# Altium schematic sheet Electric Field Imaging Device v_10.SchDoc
size A3
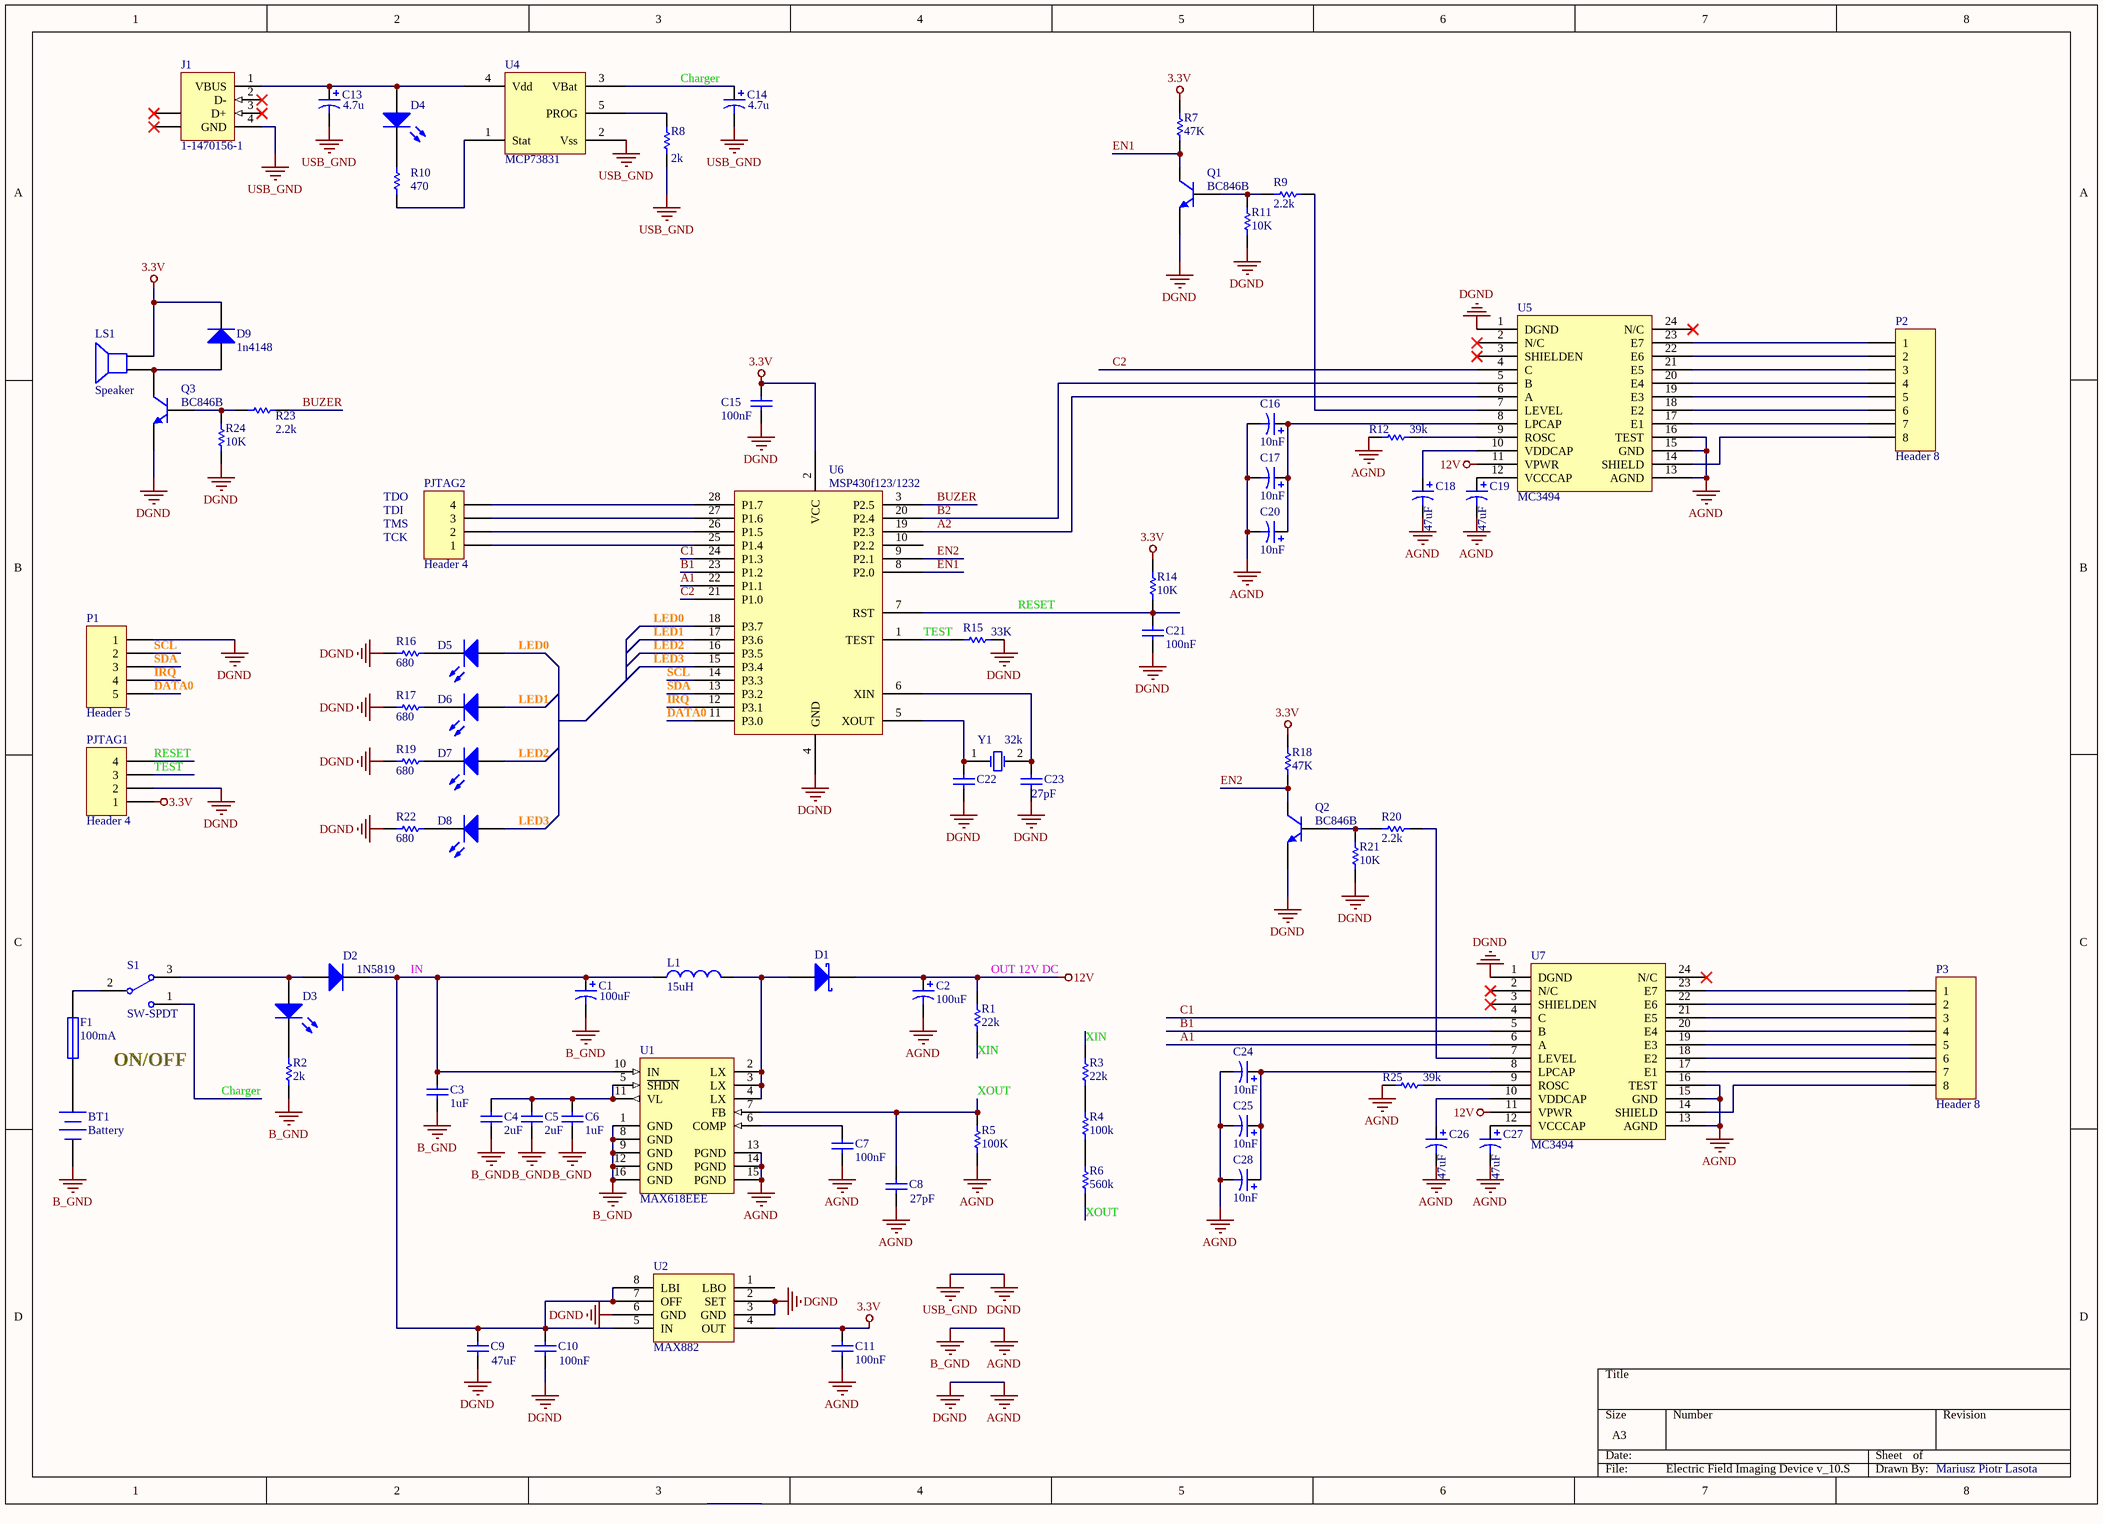
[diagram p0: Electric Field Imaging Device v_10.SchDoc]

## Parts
BT1  Battery  [6332[2512]]
C1  value 100uF  [##C_tantal_1]  (hidden comment: Cap Pol1)
C2  value 100uF  [##C_tantal_1]  (hidden comment: Cap Pol1)
C3  value 1uF  [1206]  (hidden comment: Cap)
C4  value 2uF  [1206]  (hidden comment: Cap)
C5  value 2uF  [1206]  (hidden comment: Cap)
C6  value 1uF  [1206]  (hidden comment: Cap)
C7  value 100nF  [0805]  (hidden comment: Cap)
C8  value 27pF  [0805]  (hidden comment: Cap)
C9  value 47uF  [C 100UF]  (hidden comment: Cap)
C10  value 100nF  [0805]  (hidden comment: Cap)
C11  value 100nF  [0805]  (hidden comment: Cap)
C13  value 4.7u  [##C_tantal_1]  (hidden comment: Cap Pol1)
C14  value 4.7u  [##C_tantal_1]  (hidden comment: Cap Pol1)
C15  value 100nF  [0805]  (hidden comment: Cap)
C16  value 10nF  [1206]  (hidden comment: Cap Pol1)
C17  value 10nF  [1206]  (hidden comment: Cap Pol1)
C18  value 47uF  [6332[2512]]  (hidden comment: Cap Pol1)
C19  value 47uF  [6332[2512]]  (hidden comment: Cap Pol1)
C20  value 10nF  [1206]  (hidden comment: Cap Pol1)
C21  value 100nF  [0805]  (hidden comment: Cap)
C22  27pF  [0805]  (value not drawn)
C23  27pF  [0805]
C24  value 10nF  [1206]  (hidden comment: Cap Pol1)
C25  value 10nF  [1206]  (hidden comment: Cap Pol1)
C26  value 47uF  [6332[2512]]  (hidden comment: Cap Pol1)
C27  value 47uF  [6332[2512]]  (hidden comment: Cap Pol1)
C28  value 10nF  [1206]  (hidden comment: Cap Pol1)
D1  D Schottky  [##DLAWIK_SMD_5819]  (value not drawn)
D2  NAME: 1N5819  [##DLAWIK_SMD]  (hidden comment: Diode)
D3  LED0  [0805]  (value not drawn)
D4  LED0  [0805]  (value not drawn)
D5  LED1  [0805]  (value not drawn)
D6  LED1  [0805]  (value not drawn)
D7  LED1  [0805]  (value not drawn)
D8  LED1  [0805]  (value not drawn)
D9  NAME: 1n4148  [0805DIODE]  (hidden comment: Diode)
F1  100mA  [3.2X1.6X1.1]
J1  1-1470156-1  [USB_MALE]
L1  value 15uH  [##DLAWIK_SMD]  (hidden comment: Inductor)
LS1  Speaker  [D_330uH_pionowy]
P1  Header 5  [HDR1X5]
P2  Header 8  [HDR1X8]
P3  Header 8  [HDR1X8]
PJTAG1  Header 4  [GOLDPIN4_2.54]
PJTAG2  Header 4  [GOLDPIN4_2.54]
Q1  BC846B  [SOT23_N]
Q2  BC846B  [SOT23_N]
Q3  BC846B  [SOT23_N]
R1  value 22k  [0805]  (hidden comment: Res1)
R2  value 2k  [0805]  (hidden comment: Res1)
R3  value 22k  [0805]  (hidden comment: Res1)
R4  value 100k  [0805]  (hidden comment: Res1)
R5  value 100K  [0805]  (hidden comment: Res1)
R6  value 560k  [0805]  (hidden comment: Res1)
R7  value 47K  [1206]  (hidden comment: Res1)
R8  value 2k  [0805]  (hidden comment: Res1)
R9  value 2.2k  [1206]  (hidden comment: Res1)
R10  value 470  [0805]  (hidden comment: Res1)
R11  value 10K  [1206]  (hidden comment: Res1)
R12  value 39k  [0805]  (hidden comment: Res1)
R14  value 10K  [0805]  (hidden comment: Res1)
R15  value 33K  [0805]  (hidden comment: Res1)
R16  value 680  [0805]  (hidden comment: Res1)
R17  value 680  [0805]  (hidden comment: Res1)
R18  value 47K  [1206]  (hidden comment: Res1)
R19  value 680  [0805]  (hidden comment: Res1)
R20  value 2.2k  [1206]  (hidden comment: Res1)
R21  value 10K  [1206]  (hidden comment: Res1)
R22  value 680  [0805]  (hidden comment: Res1)
R23  value 2.2k  [0805]  (hidden comment: Res1)
R24  value 10K  [0805]  (hidden comment: Res1)
R25  value 39k  [0805]  (hidden comment: Res1)
S1  SW-SPDT  [HDR1X3]
U1  MAX618EEE  [SOP16]
U2  MAX882  [SOP8_L]
U4  MCP73831  [soic_MCP73831]
U5  MC3494  [TOUCH_PANEL]
U6  MSP430f123/1232  [MSP430F1232]
U7  MC3494  [TOUCH_PANEL]
Y1  val: 32k  [kwarc_32K]  (hidden comment: XTAL)

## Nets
3.3V: C11.2 C15.2 D9.2(K) LS1.2 PJTAG1.1 R7.2 R14.2 R18.2 U2.4(OUT) U6.2(VCC)
12V: C2.1 D1.2(K) R1.2 U5.11(VPWR) U7.11(VPWR)
AGND: BT1.2(-) C1.2 C2.2 C3.1 C4.1 C5.1 C6.1 C7.1 C8.1 C9.1 C10.1 C11.1 C13.2 C14.2 C15.1 C16.2 C17.2 C18.2 C19.2 C20.2 C21.2 C22.1 C23.1 C24.2 C25.2 C26.2 C27.2 C28.2 J1.4(GND) P1.1 PJTAG1.2 Q1.2(E) Q2.2(E) Q3.2(E) R2.1 R5.1 R8.1 R11.1 R12.1 R15.2 R16.1 R17.1 R19.1 R21.1 R22.1 R24.1 R25.1 U1.1(GND) U1.8(GND) U1.9(GND) U1.12(GND) U1.13(PGND) U1.14(PGND) U1.15(PGND) U1.16(GND) U2.2(SET) U2.3(GND) U2.6(GND) U4.2(Vss) U5.1(DGND) U5.13(AGND) U5.15(GND) U5.16(TEST) U6.4(GND) U7.1(DGND) U7.13(AGND) U7.15(GND) U7.16(TEST)  [also labelled B_GND, DGND, USB_GND]
A1: U6.22(P1.1) U7.6(A)
A2: U5.6(A) U6.19(P2.3)
B1: U6.23(P1.2) U7.5(B)
B2: U5.5(B) U6.20(P2.4)
BUZER: R23.2 U6.3(P2.5)
C1: U6.24(P1.3) U7.4(C)
C2: U5.4(C) U6.21(P1.0)
Charger: C14.1 S1.1 U4.3(VBat)
DATA0: P1.5 U6.11(P3.0)
EN1: Q1.3(C) R7.1 U6.8(P2.0)
EN2: Q2.3(C) R18.1 U6.9(P2.1)
IRQ: P1.4 U6.12(P3.1)
LED0: D5.1(A) U6.18(P3.7)
LED1: D6.1(A) U6.17(P3.6)
LED2: D7.1(A) U6.16(P3.5)
LED3: D8.1(A) U6.15(P3.4)
RESET: C21.1 PJTAG1.4 R14.1 U6.7(RST)
SCL: P1.2 U6.14(P3.3)
SDA: P1.3 U6.13(P3.2)
TEST: PJTAG1.3 R15.1 U6.1(TEST)
XIN: R1.1 R3.2
XOUT: C8.2 R5.2 R6.1 U1.7(FB)
NetBT1_1: BT1.1(+) F1.1
NetC1_1: C1.1 C3.2 C9.2 C10.2 D2.2(K) L1.1 U1.10(IN) U2.5(IN) U2.7(OFF) U2.8(LBI)
NetC4_2: C4.2 C5.2 C6.2 U1.5(~{SHDN}) U1.11(VL)
NetC7_2: C7.2 U1.6(COMP)
NetC13_1: C13.1 D4.1(A) J1.1(VBUS) U4.4(Vdd)
NetC16_1: C16.1 C17.1 C20.1 U5.8(LPCAP)
NetC18_1: C18.1 U5.10(VDDCAP)
NetC19_1: C19.1 U5.12(VCCCAP)
NetC22_2: C22.2 U6.5(XOUT) Y1.1(OSC1)
NetC23_2: C23.2 U6.6(XIN) Y1.2(OSC2)
NetC24_1: C24.1 C25.1 C28.1 U7.8(LPCAP)
NetC26_1: C26.1 U7.10(VDDCAP)
NetC27_1: C27.1 U7.12(VCCCAP)
NetD1_1: D1.1(A) L1.2 U1.2(LX) U1.3(LX) U1.4(LX)
NetD2_1: D2.1(A) D3.1(A) S1.3
NetD3_2: D3.2(K) R2.2
NetD4_2: D4.2(K) R10.2
NetD5_2: D5.2(K) R16.2
NetD6_2: D6.2(K) R17.2
NetD7_2: D7.2(K) R19.2
NetD8_2: D8.2(K) R22.2
NetD9_1: D9.1(A) LS1.1 Q3.3(C)
NetF1_2: F1.2 S1.2
NetP2_1: P2.1 U5.23(E7)
NetP2_2: P2.2 U5.22(E6)
NetP2_3: P2.3 U5.21(E5)
NetP2_4: P2.4 U5.20(E4)
NetP2_5: P2.5 U5.19(E3)
NetP2_6: P2.6 U5.18(E2)
NetP2_7: P2.7 U5.17(E1)
NetP2_8: P2.8 U5.14(SHIELD)
NetP3_1: P3.1 U7.23(E7)
NetP3_2: P3.2 U7.22(E6)
NetP3_3: P3.3 U7.21(E5)
NetP3_4: P3.4 U7.20(E4)
NetP3_5: P3.5 U7.19(E3)
NetP3_6: P3.6 U7.18(E2)
NetP3_7: P3.7 U7.17(E1)
NetP3_8: P3.8 U7.14(SHIELD)
NetPJTAG2_1: PJTAG2.1 U6.25(P1.4)
NetPJTAG2_2: PJTAG2.2 U6.26(P1.5)
NetPJTAG2_3: PJTAG2.3 U6.27(P1.6)
NetPJTAG2_4: PJTAG2.4 U6.28(P1.7)
NetQ1_1: Q1.1(B) R9.1 R11.2
NetQ2_1: Q2.1(B) R20.1 R21.2
NetQ3_1: Q3.1(B) R23.1 R24.2
NetR3_1: R3.1 R4.1
NetR4_2: R4.2 R6.2
NetR8_2: R8.2 U4.5(PROG)
NetR9_2: R9.2 U5.7(LEVEL)
NetR10_1: R10.1 U4.1(Stat)
NetR12_2: R12.2 U5.9(ROSC)
NetR20_2: R20.2 U7.7(LEVEL)
NetR25_2: R25.2 U7.9(ROSC)

Not connected (* = marked no-connect by the designer): J1 2(D-)* 3(D+)* 5(SHLD)* 6(SHLD)*; U2 1(LBO); U5 2(N/C)* 3(SHIELDEN)* 24(N/C)*; U6 10(P2.2); U7 2(N/C)* 3(SHIELDEN)* 24(N/C)*

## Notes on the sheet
- TDO
- TDI
- TMS
- TCK
- IN
- (near R1) OUT 12V DC
- ON/OFF
- Mariusz Piotr Lasota

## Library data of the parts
BT1 = Battery: Multicell Battery
C1 C2 C13 C14 C16-C20 C24-C28 = Cap Pol1: Polarized Capacitor (Radial)
C3-C11 C15 C21-C23 = Cap: Capacitor
D1 = D Schottky: Schottky Diode; val: 1N5819
D2 D9 = Diode: Default Diode
D3 D4 = LED0: Typical INFRARED GaAs LED
D5-D8 = LED1: Typical RED GaAs LED
F1 = Fuse 1: Fuse
J1 = 1-1470156-1: USB 1.1, Right Angle, Thru-Hole, B Type, Receptacle, 4 Position, White; ContactMaterial: Phosphor Bronze; ContactPlating: Gold over Nickel; TerminationLength: 3.00mm [0.118in.]; PCB_Layout: Complies with manufacturer's recommendation.; DrillSize: Corresponds to nominal value.; PanelGround: Without
L1 = Inductor: Code_IEC: 1005
LS1 = Speaker: Loudspeaker
P1 = Header 5: Header, 5-Pin
P2 P3 = Header 8: Header, 8-Pin
PJTAG1 PJTAG2 = Header 4: Header, 4-Pin
Q1-Q3 = BC850B: NPN General-purpose Transistor
R1-R12 R14-R25 = Res1: Resistor
S1 = SW-SPDT: SPDT Subminiature Toggle Switch, Right Angle Mounting, Vertical Actuation
U1 = MAX618EEE: 28V, PWM, Step-UP DC-DC Converter
U6 = msp430f1232
Y1 = XTAL: Crystal Oscillator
